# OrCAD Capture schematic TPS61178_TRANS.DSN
size D; title: TPS61178: TPS61178x 20-V, 10-A Fully-Integrated Synchronous; rev: 1.0; note: Datasheet: SLVSDA7     EVM: SLVUB05; note: Synchronous Step Down Converter
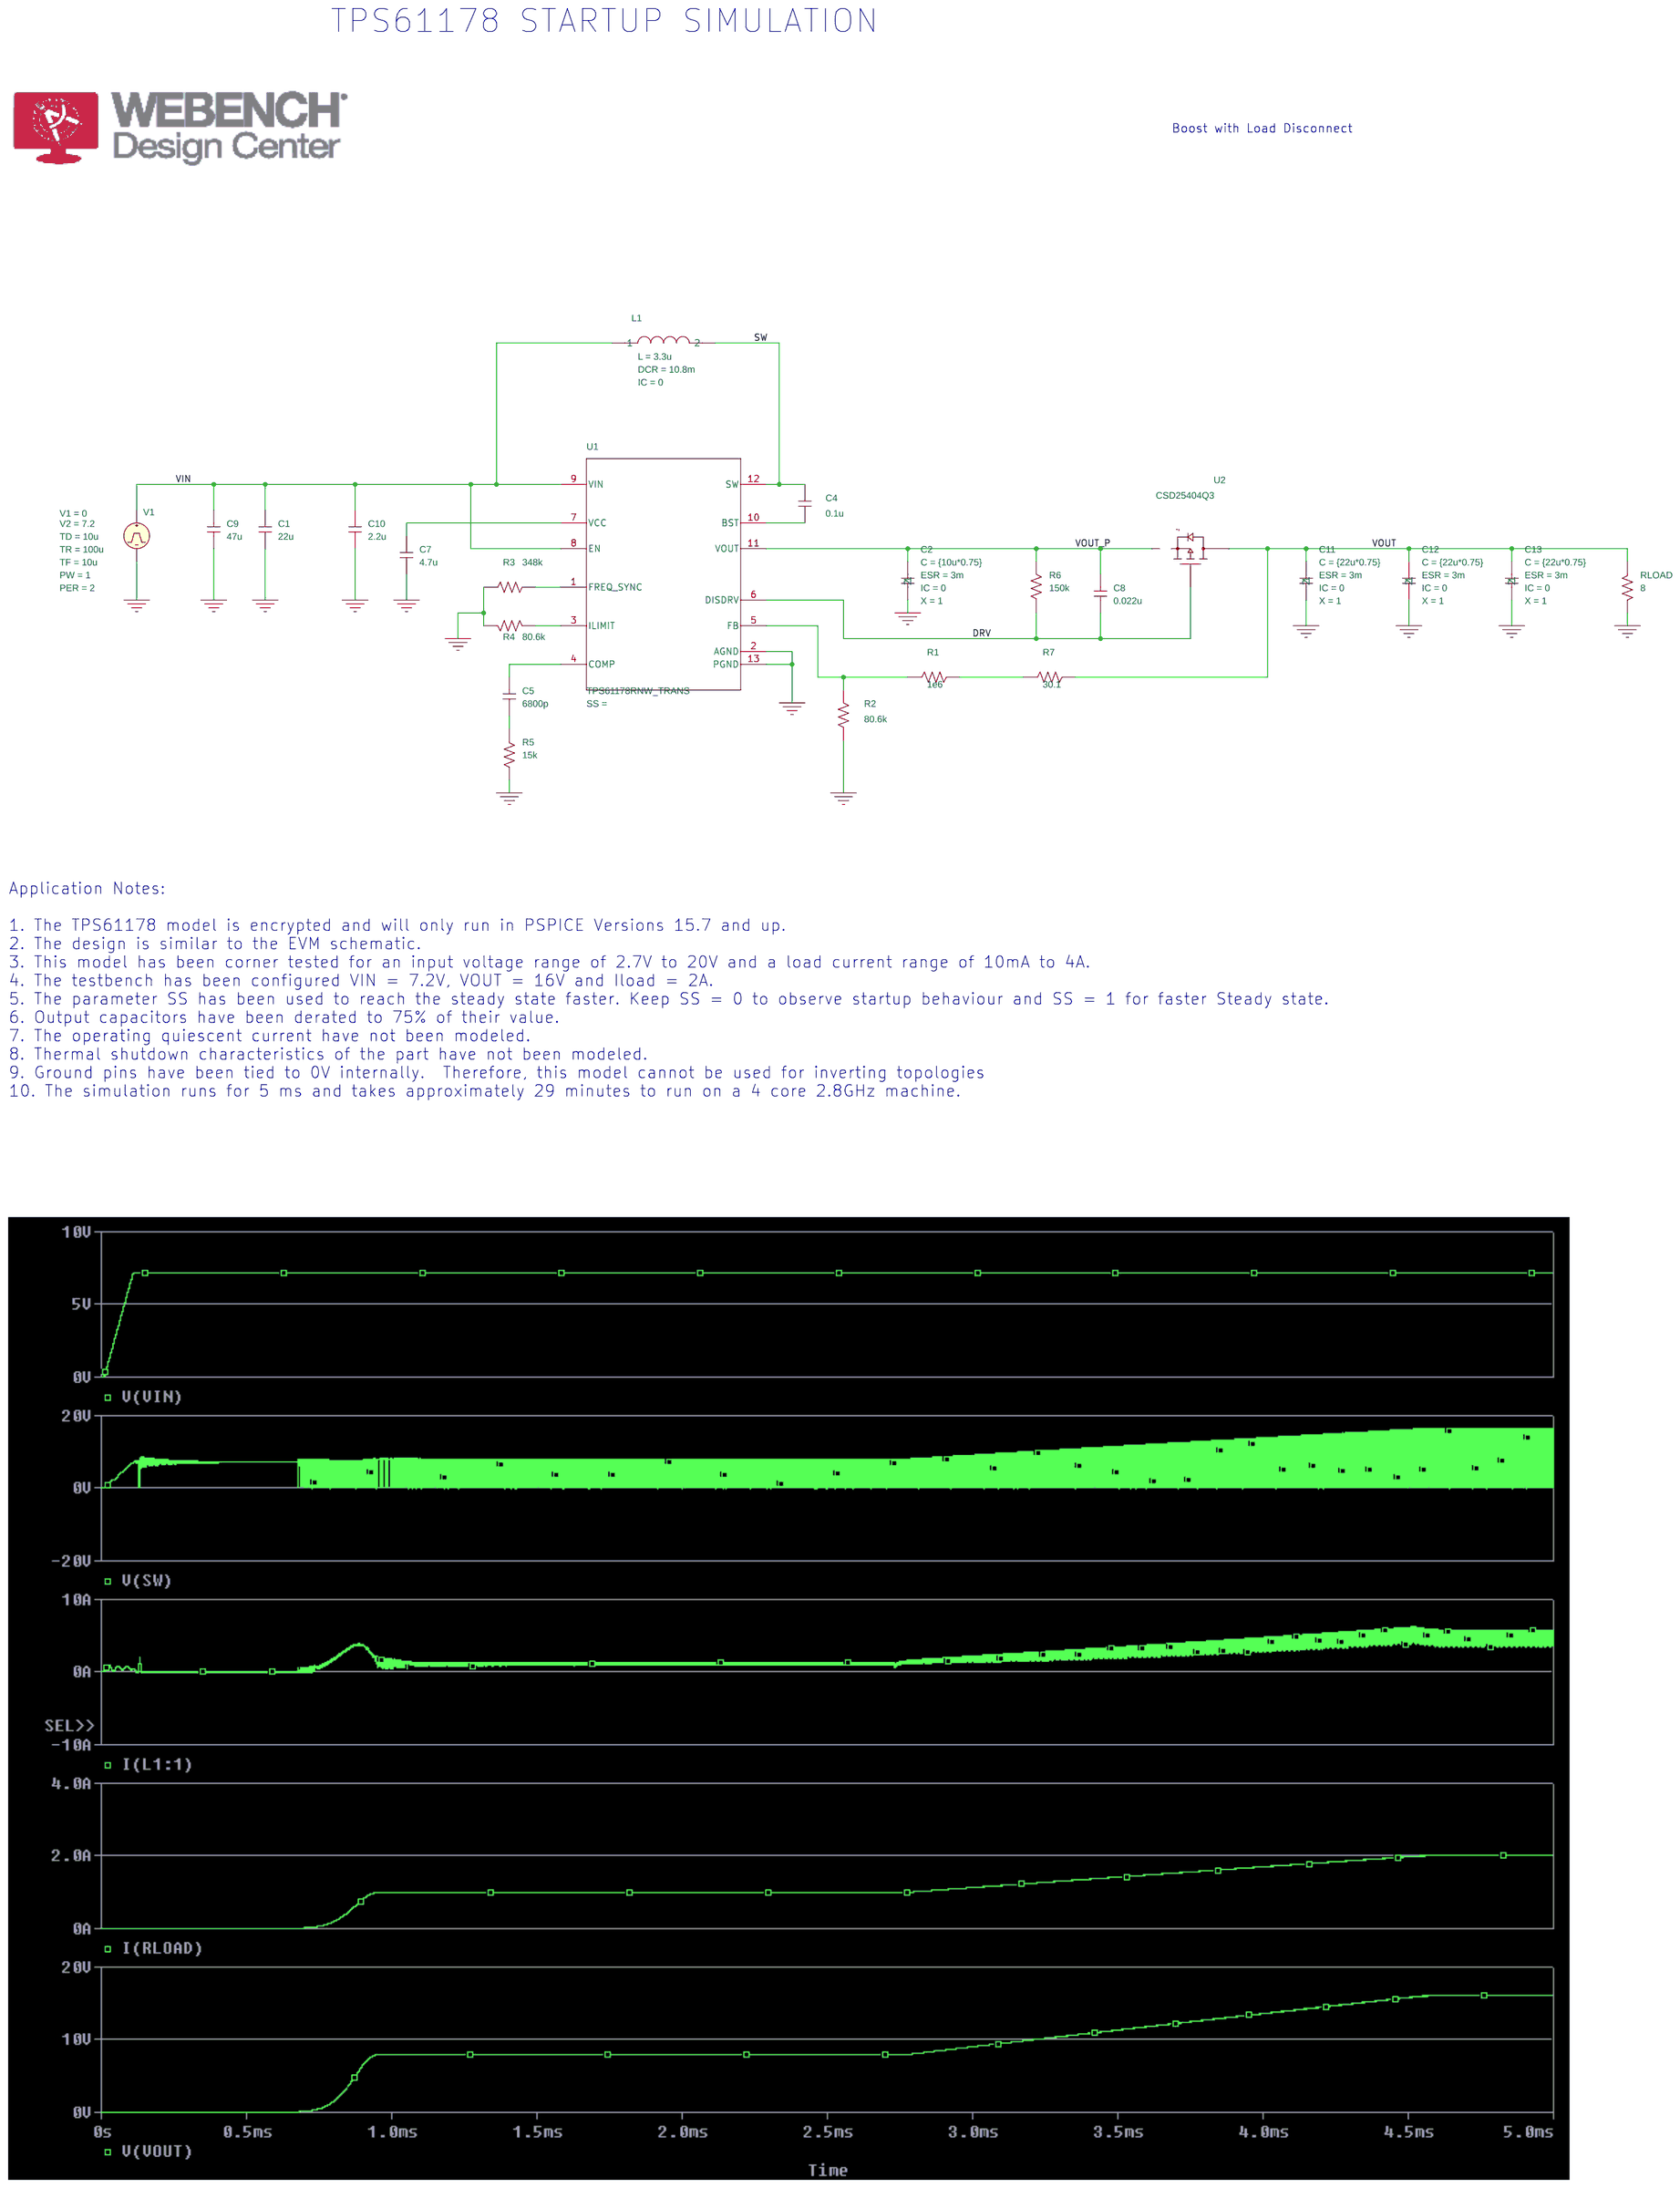
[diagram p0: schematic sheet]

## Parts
C1  22u  [RAD/CK05]
C2  CESR
C4  0.1u  [RAD/CK05]
C5  6800p  [RAD/CK05]
C7  4.7u  [RAD/CK05]
C8  0.022u  [RAD/CK05]
C9  47u  [RAD/CK05]
C10  2.2u  [RAD/CK05]
C11  CESR
C12  CESR
C13  CESR
L1  LDCR
R1  1e6  [AX/RC05]
R2  80.6k  [AX/RC05]
R3  348k  [AX/RC05]
R4  80.6k  [AX/RC05]
R5  15k  [AX/RC05]
R6  150k  [AX/RC05]
R7  30.1  [AX/RC05]
RLOAD  8  [AX/RC05]
U1  TPS61178RNW_TRANS  [RNW0013A]
U2  CSD25404Q3
V1  VPULSE

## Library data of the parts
C1 C4 C5 C7-C10 = C
C2 = CESR_1_2: C: {10u*0.75}; ESR: 3m; IC: 0; PSpiceTemplate: X^@REFDES %1 %2 @MODEL PARAMS: ?C|C=@C||C=10U| ?ESR|ESR=@ESR||ESR=2M| ?IC|IC=@IC||IC=0| ?X|X=@X||X=0|; X: 1
C11 = CESR_1_3: C: {22u*0.75}; ESR: 3m; IC: 0; PSpiceTemplate: X^@REFDES %1 %2 @MODEL PARAMS: ?C|C=@C||C=10U| ?ESR|ESR=@ESR||ESR=2M| ?IC|IC=@IC||IC=0| ?X|X=@X||X=0|; X: 1
C12 = CESR_1_1: C: {22u*0.75}; ESR: 3m; IC: 0; PSpiceTemplate: X^@REFDES %1 %2 @MODEL PARAMS: ?C|C=@C||C=10U| ?ESR|ESR=@ESR||ESR=2M| ?IC|IC=@IC||IC=0| ?X|X=@X||X=0|; X: 1
C13 = CESR_1: C: {22u*0.75}; ESR: 3m; IC: 0; PSpiceTemplate: X^@REFDES %1 %2 @MODEL PARAMS: ?C|C=@C||C=10U| ?ESR|ESR=@ESR||ESR=2M| ?IC|IC=@IC||IC=0| ?X|X=@X||X=0|; X: 1
L1 = LDCR: DCR: 10.8m; IC: 0; L: 3.3u; PSpiceTemplate: X^@REFDES %1 %2 @MODEL PARAMS: ?L|L=@L||L=10U| ?DCR|DCR=@DCR||DCR=20M| ?IC|IC=@IC||IC=0|
R1-R7 RLOAD = R
U1 = TPS61178RNW_TRANS
U2 = CSD25404Q3
V1 = VPULSE: PER: 2; PW: 1; TD: 10u; TF: 10u; TR: 100u; V1: 0; V2: 7.2

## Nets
VIN: C1.1 C9.1 C10.1 L1.1 U1.8(EN) U1.9(VIN) V1.1(+)
0: C1.2 C2.2 C7.2 C9.2 C10.2 C11.2 C12.2 C13.2 R2.1 R3.1 R4.1 R5.2 RLOAD.2 U1.2(AGND) U1.13(PGND) V1.2(-)
DRV: C8.2 R6.1 U1.6(DISDRV) U2.2(gate)
SW: C4.2 L1.2 U1.12(SW)
VOUT: C11.1 C12.1 C13.1 R7.2 RLOAD.1 U2.3(drain)
VOUT_P: C2.1 C8.1 R6.2 U1.11(VOUT) U2.1(source)
N16770317: C7.1 U1.7(VCC)
N16770637: C4.1 U1.10(BST)
N16770943: R1.1 R2.2 U1.5(FB)
N16770965: R1.2 R7.1
N16776827: R4.2 U1.3(ILIMIT)
N16776833: R3.2 U1.1(FREQ_SYNC)
N16776875: C5.2 R5.1
N16776895: C5.1 U1.4(COMP)

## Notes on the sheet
- TPS61178 STARTUP SIMULATION
- Boost with Load Disconnect
- Application Notes:
  1. The TPS61178 model is encrypted and will only run in PSPICE Versions 15.7 and up.
  2. The design is similar to the EVM schematic.
  3. This model has been corner tested for an input voltage range of 2.7V to 20V and a load current range of 10mA to 4A.
  4. The testbench has been configured VIN = 7.2V, VOUT = 16V and Iload = 2A.
  5. The parameter SS has been used to reach the steady state faster. Keep SS = 0 to observe startup behaviour and SS = 1 for faster Steady state.
  6. Output capacitors have been derated to 75% of their value.
  7. The operating quiescent current have not been modeled.
  8. Thermal shutdown characteristics of the part have not been modeled.
  9. Ground pins have been tied to 0V internally.  Therefore, this model cannot be used for inverting topologies
  10. The simulation runs for 5 ms and takes approximately 29 minutes to run on a 4 core 2.8GHz machine.
